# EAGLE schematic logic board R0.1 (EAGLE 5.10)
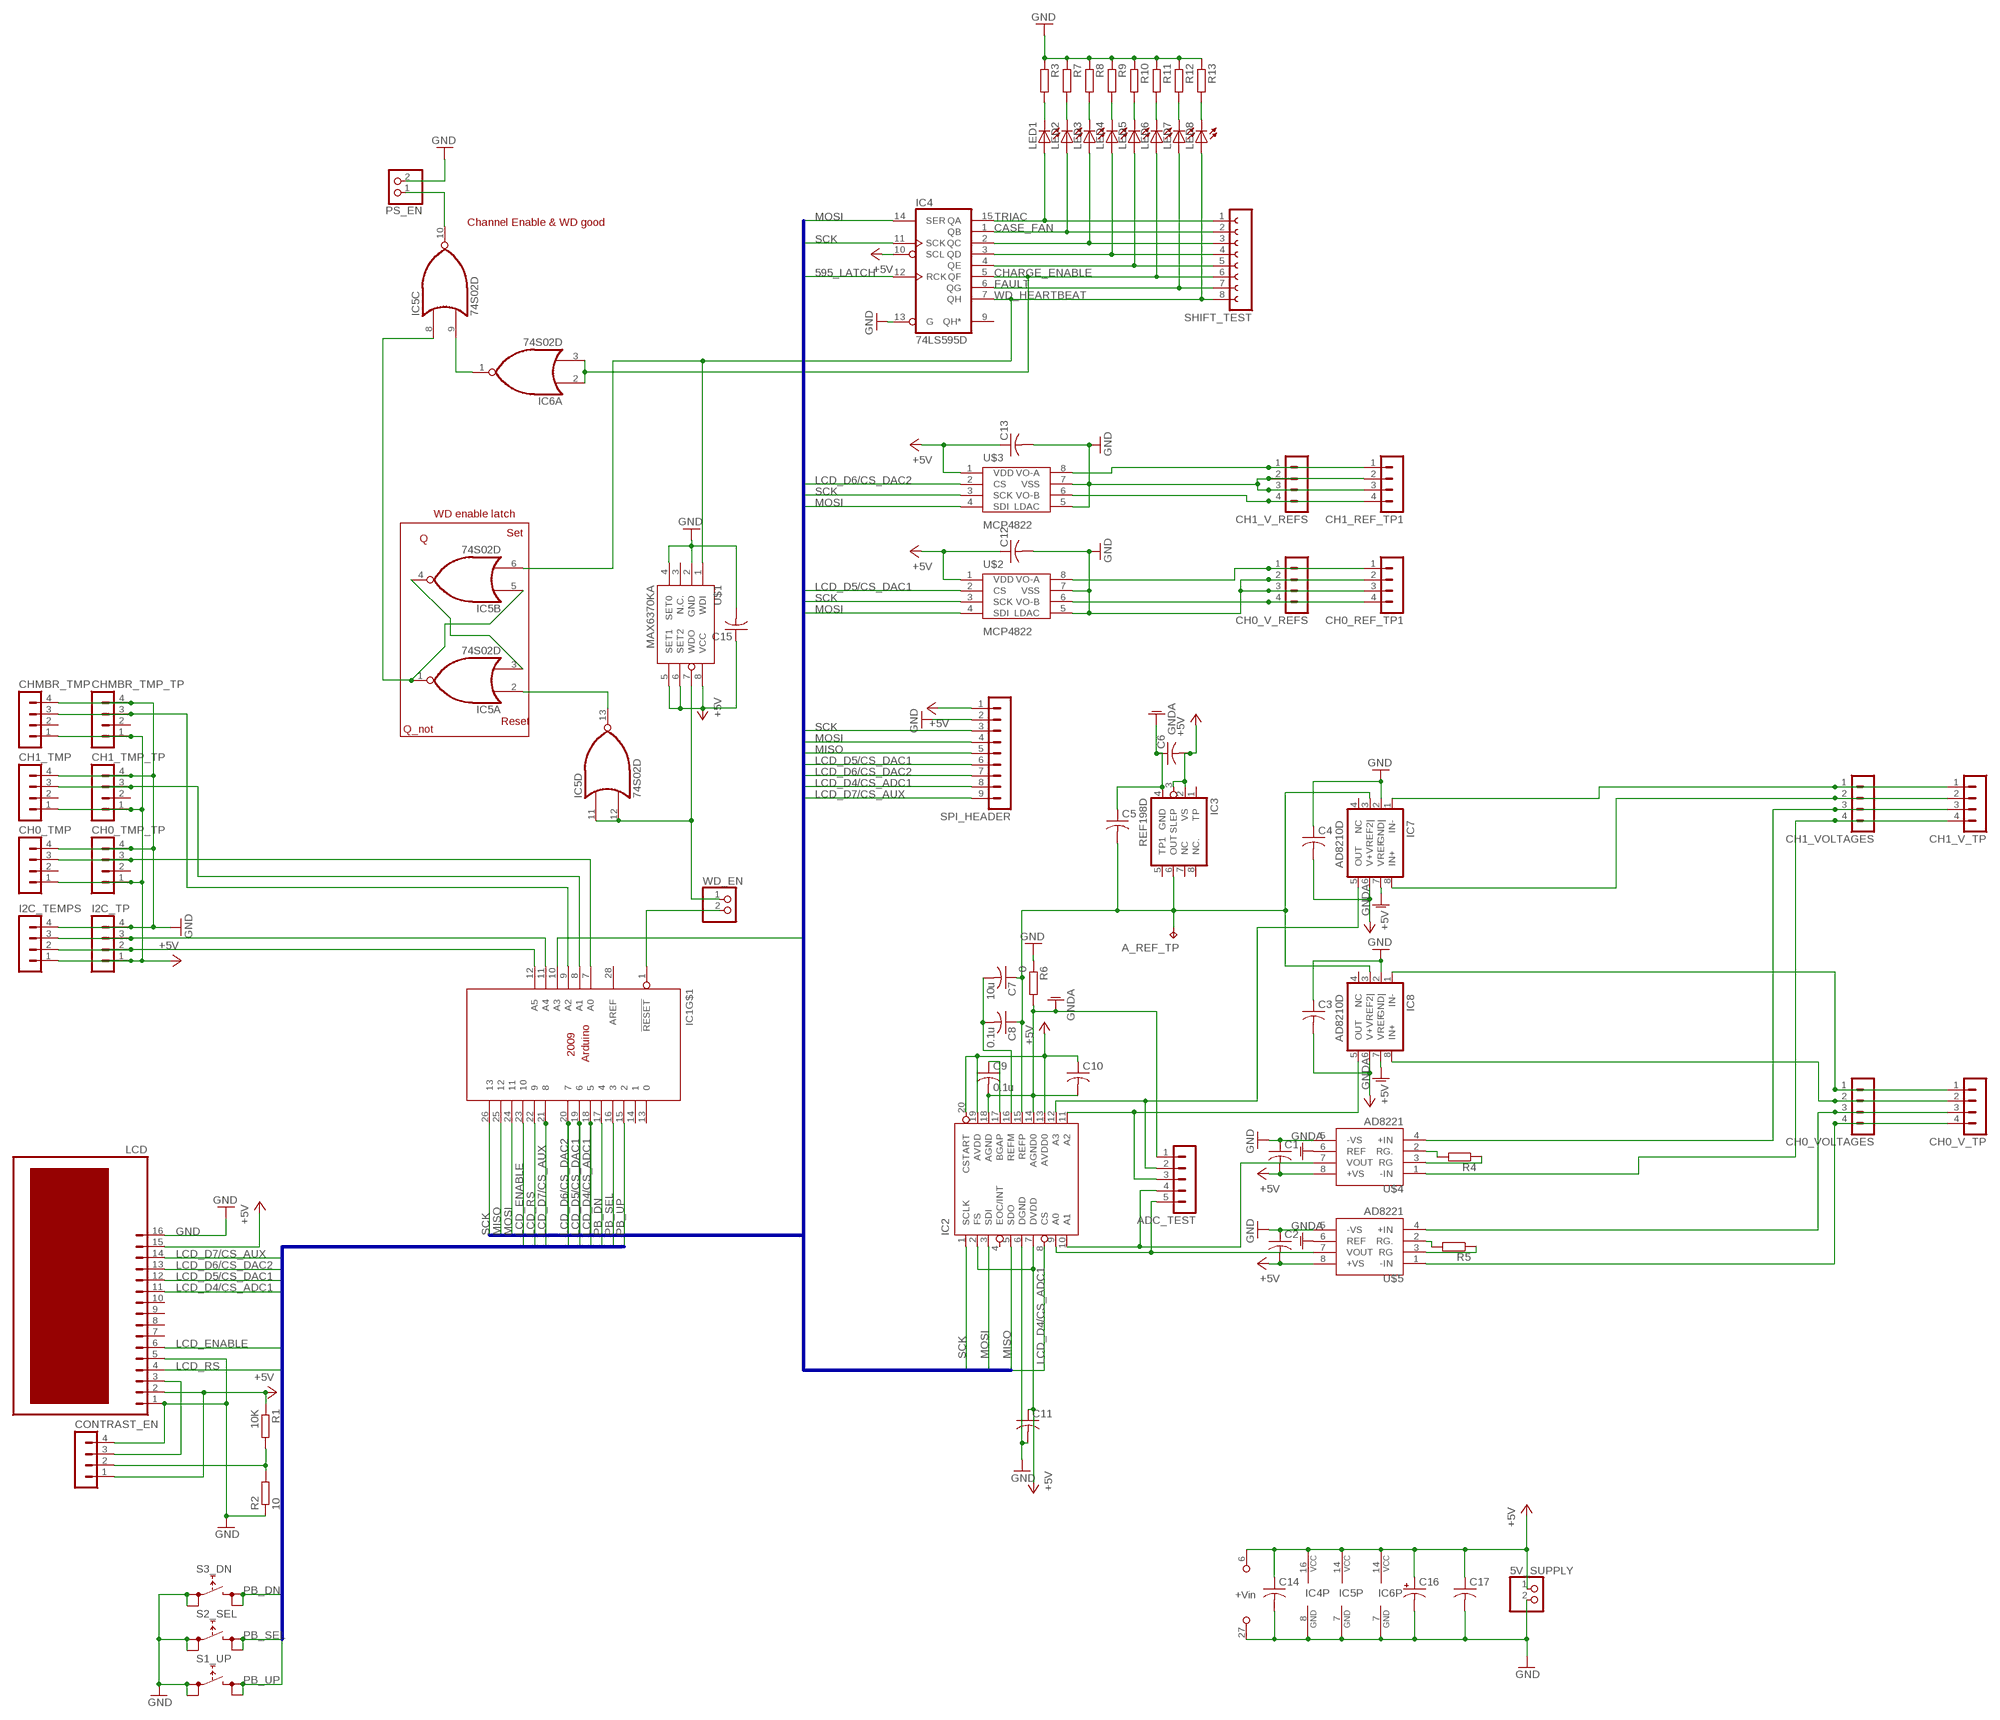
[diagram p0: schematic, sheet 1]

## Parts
5V_SUPPLY  PINHD-1X2  [1X02]
A_REF_TP  TPPAD1-13Y  [P1-13Y]
ADC_TEST  MA05-1  [MA05-1]
C1  C-USC0805  [C0805]
C2  C-USC0805  [C0805]
C3  C-USC0805  [C0805]
C4  C-USC0805  [C0805]
C5  C-USC0805  [C0805]
C6  C-USC0805  [C0805]
C7  10u  C-USC0805  [C0805]
C8  0.1u  C-USC0805  [C0805]
C9  0.1u  C-USC0805  [C0805]
C10  C-USC0805  [C0805]
C11  C-USC0805  [C0805]
C12  C-USC0805  [C0805]
C13  C-USC0805  [C0805]
C14  C-USC0805  [C0805]
C15  C-USC0805  [C0805]
C16  CPOL-USE7.5-16  [E7,5-16]
C17  C-US075-052X106  [C075-052X106]
CH0_REF_TP1  MA04-1  [MA04-1]
CH0_TMP  4PIN-HORIZONTAL  [4PIN_HORIZONTAL]
CH0_TMP_TP  MA04-1  [MA04-1]
CH0_V_REFS  4PIN-HORIZONTAL  [4PIN_HORIZONTAL]
CH0_V_TP  MA04-1  [MA04-1]
CH0_VOLTAGES  4PIN-HORIZONTAL  [4PIN_HORIZONTAL]
CH1_REF_TP1  MA04-1  [MA04-1]
CH1_TMP  4PIN-HORIZONTAL  [4PIN_HORIZONTAL]
CH1_TMP_TP  MA04-1  [MA04-1]
CH1_V_REFS  4PIN-HORIZONTAL  [4PIN_HORIZONTAL]
CH1_V_TP  MA04-1  [MA04-1]
CH1_VOLTAGES  4PIN-HORIZONTAL  [4PIN_HORIZONTAL]
CHMBR_TMP  4PIN-HORIZONTAL  [4PIN_HORIZONTAL]
CHMBR_TMP_TP  MA04-1  [MA04-1]
CONTRAST_EN  MA04-1  [MA04-1]
I2C_TEMPS  4PIN-HORIZONTAL  [4PIN_HORIZONTAL]
I2C_TP  MA04-1  [MA04-1]
IC1  ARDUINO2009_20  [ARDUINO2009]
IC2  TLC3544D  [SO20W]
IC3  REF198D  [SO08]
IC4  74LS595D  [SO16]
IC5  74S02D  [SO14]
IC6  74S02D  [SO14]
IC7  AD8210D  [SO08]
IC8  AD8210D  [SO08]
LCD  HDM16216L-5  [HDM16216L-5]
LED1  LEDCHIP-LED0805  [CHIP-LED0805]
LED2  LEDCHIP-LED0805  [CHIP-LED0805]
LED3  LEDCHIP-LED0805  [CHIP-LED0805]
LED4  LEDCHIP-LED0805  [CHIP-LED0805]
LED5  LEDCHIP-LED0805  [CHIP-LED0805]
LED6  LEDCHIP-LED0805  [CHIP-LED0805]
LED7  LEDCHIP-LED0805  [CHIP-LED0805]
LED8  LEDCHIP-LED0805  [CHIP-LED0805]
PS_EN  PINHD-1X2  [1X02]
R1  10K  R-EU_R0805  [R0805]
R2  10  R-EU_R0805  [R0805]
R3  R-EU_R0805  [R0805]
R4  R-EU_R0805  [R0805]
R5  R-EU_R0805  [R0805]
R6  0  R-EU_R0805  [R0805]
R7  R-EU_R0805  [R0805]
R8  R-EU_R0805  [R0805]
R9  R-EU_R0805  [R0805]
R10  R-EU_R0805  [R0805]
R11  R-EU_R0805  [R0805]
R12  R-EU_R0805  [R0805]
R13  R-EU_R0805  [R0805]
S1_UP  REKN  [REKN]
S2_SEL  REKN  [REKN]
S3_DN  REKN  [REKN]
SHIFT_TEST  FE08-1  [FE08]
SPI_HEADER  MA09-1  [MA09-1]
U$1  MAX6370KA  [SOT23-8]
U$2  MCP4822  [SO08]
U$3  MCP4822  [SO08]
U$4  AD8221  [SO08]
U$5  AD8221  [SO08]
WD_EN  PINHD-1X2  [1X02]

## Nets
595_LATCH: IC1.10(A3) IC4.12(RCK)
+5V: 5V_SUPPLY.1 C1.2 C2.2 C3.2 C4.2 C6.2 C10.1 C11.1 C12.1 C13.1 C14.1 C15.1 C16.+ C17.1 CH0_TMP.1 CH0_TMP_TP.1 CH1_TMP.1 CH1_TMP_TP.1 CHMBR_TMP.1 CHMBR_TMP_TP.1 CONTRAST_EN.1 I2C_TEMPS.1 I2C_TP.1 IC1.6(+VIN) IC2.2(FS) IC2.7(DVDD) IC2.13(AVDD0) IC2.19(AVDD) IC2.20(CSTART) IC3.2(VS) IC3.3(SLEP) IC4.10(SCL) IC4.16(VCC) IC5.14(P:VCC) IC6.14(P:VCC) IC7.6(V+) IC8.6(V+) LCD.2 LCD.15 R1.1 SPI_HEADER.1 U$1.5(SET1) U$1.6(SET2) U$1.8(VCC) U$2.1(VDD) U$3.1(VDD) U$4.8(+VS) U$5.8(+VS)
CASE_FAN: IC4.1(QB) LED2.A SHIFT_TEST.2
CHARGE_ENABLE: IC4.5(QF) IC6.2(A:I0) IC6.3(A:I1) LED6.A SHIFT_TEST.6
FAULT: IC4.6(QG) LED7.A SHIFT_TEST.7
GND: 5V_SUPPLY.2 C1.1 C2.1 C3.1 C4.1 C11.2 C12.2 C13.2 C14.2 C15.2 C16.- C17.2 CH0_REF_TP1.2 CH0_REF_TP1.3 CH0_TMP.4 CH0_TMP_TP.4 CH0_V_REFS.2 CH0_V_REFS.3 CH1_REF_TP1.2 CH1_REF_TP1.3 CH1_TMP.4 CH1_TMP_TP.4 CH1_V_REFS.2 CH1_V_REFS.3 CHMBR_TMP.4 CHMBR_TMP_TP.4 CONTRAST_EN.4 I2C_TEMPS.4 I2C_TP.4 IC1.27(GND) IC2.6(DGND) IC4.8(GND) IC4.13(G) IC5.7(P:GND) IC6.7(P:GND) IC7.2(GND|) IC8.2(GND|) LCD.1 LCD.5 LCD.16 PS_EN.2 R2.1 R3.1 R6.1 R7.1 R8.1 R9.1 R10.1 R11.1 R12.1 R13.1 S1_UP.1A S1_UP.1B S2_SEL.1A S2_SEL.1B S3_DN.1A S3_DN.1B SPI_HEADER.2 U$1.2(GND) U$1.4(SET0) U$2.5(LDAC) U$2.7(VSS) U$3.5(LDAC) U$3.7(VSS) U$4.5(-VS) U$5.5(-VS)
GNDA: ADC_TEST.1 C5.1 C6.1 C9.2 C10.2 IC2.14(AGND0) IC2.18(AGND) IC3.4(GND) IC7.7(VREF) IC8.7(VREF) R6.2 U$4.6(REF) U$5.6(REF)
LCD_D4/CS_ADC1: IC1.18 IC2.8(CS) LCD.11 SPI_HEADER.8
LCD_D5/CS_DAC1: IC1.19 LCD.12 SPI_HEADER.6 U$2.2(CS)
LCD_D6/CS_DAC2: IC1.20 LCD.13 SPI_HEADER.7 U$3.2(CS)
LCD_D7/CS_AUX: IC1.21 LCD.14 SPI_HEADER.9
LCD_ENABLE: IC1.23 LCD.6
LCD_RS: IC1.22 LCD.4
MISO: IC1.25 IC2.5(SDO) SPI_HEADER.5
MOSI: IC1.24 IC2.3(SDI) IC4.14(SER) SPI_HEADER.4 U$2.4(SDI) U$3.4(SDI)
N$1: CONTRAST_EN.3 LCD.3
N$2: R4.2 U$4.2(RG.)
N$3: R4.1 U$4.3(RG)
N$4: R5.2 U$5.2(RG.)
N$5: R5.1 U$5.3(RG)
N$6: CH1_V_TP.3 CH1_VOLTAGES.3 U$4.4(+IN)
N$7: CH1_V_TP.4 CH1_VOLTAGES.4 U$4.1(-IN)
N$8: CH0_V_TP.3 CH0_VOLTAGES.3 U$5.4(+IN)
N$9: CH0_V_TP.4 CH0_VOLTAGES.4 U$5.1(-IN)
N$10: A_REF_TP.TP C5.2 C7.1 C8.1 IC2.15(REFP) IC3.6(OUT) IC7.3(VREF2|) IC8.3(VREF2|)
N$11: C7.2 C8.2 IC2.16(REFM)
N$13: C9.1 IC2.17(BGAP)
N$14: ADC_TEST.2 IC2.12(A3) IC7.5(OUT)
N$15: ADC_TEST.3 IC2.11(A2) IC8.5(OUT)
N$16: ADC_TEST.4 IC2.10(A1) U$4.7(VOUT)
N$17: ADC_TEST.5 IC2.9(A0) U$5.7(VOUT)
N$18: IC1.1(!RESET) WD_EN.2
N$19: IC5.1(A:O) IC5.5(B:I0) IC5.8(C:I0)
N$20: IC5.3(A:I1) IC5.4(B:O)
N$21: IC5.11(D:I0) IC5.12(D:I1) U$1.7(WDO) WD_EN.1
N$22: IC5.9(C:I1) IC6.1(A:O)
N$24: IC5.2(A:I0) IC5.13(D:O)
N$25: CH0_V_TP.2 CH0_VOLTAGES.2 IC8.8(IN+)
N$26: CH0_V_TP.1 CH0_VOLTAGES.1 IC8.1(IN-)
N$27: CH1_V_TP.2 CH1_VOLTAGES.2 IC7.8(IN+)
N$28: CH1_V_TP.1 CH1_VOLTAGES.1 IC7.1(IN-)
N$29: CH1_REF_TP1.4 CH1_V_REFS.4 U$3.6(VO-B)
N$30: CH1_REF_TP1.1 CH1_V_REFS.1 U$3.8(VO-A)
N$31: CH0_REF_TP1.1 CH0_V_REFS.1 U$2.8(VO-A)
N$32: CH0_REF_TP1.4 CH0_V_REFS.4 U$2.6(VO-B)
N$33: IC5.10(C:O) PS_EN.1
N$36: IC4.2(QC) LED3.A SHIFT_TEST.3
N$37: IC4.3(QD) LED4.A SHIFT_TEST.4
N$38: IC4.4(QE) LED5.A SHIFT_TEST.5
N$40: LED1.C R3.2
N$41: LED2.C R7.2
N$42: LED3.C R8.2
N$43: LED4.C R9.2
N$44: LED5.C R10.2
N$45: LED6.C R11.2
N$46: LED7.C R12.2
N$47: LED8.C R13.2
N$48: CONTRAST_EN.2 R1.2 R2.2
N$49: I2C_TEMPS.2 I2C_TP.2 IC1.12(A5)
N$50: I2C_TEMPS.3 I2C_TP.3 IC1.11(A4)
N$57: CHMBR_TMP.3 CHMBR_TMP_TP.3 IC1.9(A2)
N$58: CH1_TMP.3 CH1_TMP_TP.3 IC1.8(A1)
N$59: CH0_TMP.3 CH0_TMP_TP.3 IC1.7(A0)
PB_DN: IC1.17 S3_DN.2A S3_DN.2B
PB_SEL: IC1.16 S2_SEL.2A S2_SEL.2B
PB_UP: IC1.15 S1_UP.2A S1_UP.2B
SCK: IC1.26 IC2.1(SCLK) IC4.11(SCK) SPI_HEADER.3 U$2.3(SCK) U$3.3(SCK)
TRIAC: IC4.15(QA) LED1.A SHIFT_TEST.1
WD_HEARTBEAT: IC4.7(QH) IC5.6(B:I1) LED8.A SHIFT_TEST.8 U$1.1(WDI)
Unconnected: CH0_TMP.2 CH0_TMP_TP.2 CH1_TMP.2 CH1_TMP_TP.2 CHMBR_TMP.2 CHMBR_TMP_TP.2 IC1.13 IC1.14 IC1.28(AREF) IC2.4(EOC/INT) IC3.1(TP) IC3.7(NC) IC3.8(NC.) IC4.9(QH*) IC6.4(B:O) IC6.5(B:I0) IC6.6(B:I1) IC6.8(C:I0) IC6.9(C:I1) IC6.10(C:O) IC6.11(D:I0) IC6.12(D:I1) IC6.13(D:O) LCD.7 LCD.8 LCD.9 LCD.10 U$1.3(N.C.)

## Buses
MOSI,MISO,SCK,LCD_D5/CS_DAC1,LCD_D6/CS_DAC2,LCD_D4/CS_ADC1,595_LATCH,LCD_D7/CS_AUX
LCD_D7/CS_AUX,LCD_D5/CS_DAC1,LCD_D6/CS_DAC2,LCD_D4/CS_ADC1,LCD_RS,LCD_ENABLE,PB_DN,PB_SEL,PB_UP

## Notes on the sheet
- Channel Enable & WD good
- WD enable latch
- Set
- Q
- Q_not | Reset

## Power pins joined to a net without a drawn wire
+3V3: IC1.2(+3V3)
+5V: IC1.3(+5V)
GND: IC1.4(GND) IC1.5(GND)
NC: IC7.4(NC) IC8.4(NC)
TP1: IC3.5(TP1)

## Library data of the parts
5V_SUPPLY PS_EN WD_EN = pinhead:PINHD-1X2: PIN HEADER
A_REF_TP = testpad:TP: Test pad
ADC_TEST = con-lstb:MA05-1: PIN HEADER
C1-C15 C17 = rcl:C-US: CAPACITOR, American symbol
C16 = rcl:CPOL-US: POLARIZED CAPACITOR, American symbol
CH0_REF_TP1 CH0_TMP_TP CH0_V_TP CH1_REF_TP1 CH1_TMP_TP CH1_V_TP CHMBR_TMP_TP CONTRAST_EN I2C_TP = con-lstb:MA04-1: PIN HEADER
CH0_TMP CH0_V_REFS CH0_VOLTAGES CH1_TMP CH1_V_REFS CH1_VOLTAGES CHMBR_TMP I2C_TEMPS = NEWPARTS:4PIN-HORIZONTAL: PIN HEADER
IC1 = arduino:ARDUINO2009_2: The Arduino Duemilanove ("2009") is a microcontroller board based on the ATmega168 or ATmega328. - 14 digital input/output pins (of which 6 can be used as PWM outputs) - 6 analog inputs, a 16 MHz crystal oscillator - USB connection - power jack - ISP header - reset button It contains everything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
IC2 = NEWPARTS:TLC3544: A/D CONVERTER
IC3 = NEWPARTS:REF198: Precision Micropower, Low Dropout Voltage References
IC4 = 74xx-us:74*595: 8-bit SHIFT REGISTER, output latch
IC5 IC6 = 74xx-us:74*02: Quad 2-input NOR gate
IC7 IC8 = NEWPARTS:AD8210: High Voltage, Bidirectional Current Shunt Monitor
LCD = NEWPARTS:HDM16216L-5: PIN HEADER
LED1-LED8 = led:LED: LED
R1-R13 = rcl:R-EU_: RESISTOR, European symbol
S1_UP S2_SEL S3_DN = NEWPARTS:REKN: PUSH SWITCH ITT-Cannon-Cannon
SHIFT_TEST = con-lsta:FE08-1: FEMALE HEADER
SPI_HEADER = con-lstb:MA09-1: PIN HEADER
U$1 = NEWPARTS:MAX6370KA
U$2 U$3 = NEWPARTS:MCP4822
U$4 U$5 = NEWPARTS:AD8221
